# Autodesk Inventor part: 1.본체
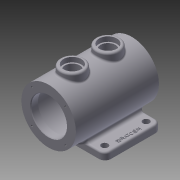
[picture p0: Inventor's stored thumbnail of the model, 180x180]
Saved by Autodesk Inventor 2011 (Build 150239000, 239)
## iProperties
Created: 2014-12
Part Number: 1.본체
Document SubType Name: Modeling
Designer: user
Density: 2.71 g/cm^3
Material: 알루미늄-6061
Mass: 1278.07 g
Surface Area: 1072.68 cm^2
Volume: 471.612 cm^3
Author: user
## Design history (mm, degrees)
sketch "스케치1"
  geometry: L1 (-65, -47.5)-(65, -47.5); L2 (65, -47.5)-(65, 47.5); L3 (65, 47.5)-(-65, 47.5); L4 (-65, 47.5)-(-65, -47.5); L5 (-65, -47.5)-(65, 47.5); 2 further points
  constraints: 11 end point, 2 parallel, 1 coincident, 1 horizontal, 1 midpoint, 1 perpendicular
  dimensions: "d0" = 130 distance of L2.end L3.end; "d1" = 95 distance of L3.end L1.start
extrude "돌출1" new body sketch "스케치1" distance "d2" = 12; taper "d3" = 0 deg
node "작업 평면1"
sketch "스케치2"
  geometry: L1 (0, -12)-(130, -12) reference; L2 (130, 0)-(130, -12) reference; L3 (130, 0)-(0, 0) reference; L4 (0, 0)-(0, -12) reference; C1 r 46 at (65, -50); 2 further points
  constraints: 1 centre point, 1 midpoint, 1 vertical alignment
  dimensions: "d5" = 92 diameter of C1; "d6" = 50 distance from line of L3 C1.centre
extrude "돌출2" join sketch "스케치2" distance "d7" = 140; taper "d8" = 0 deg
sketch "스케치3"
  geometry: L1 (-77.5, 96)-(62.5, 96) reference; L2 (62.5, 96)-(62.5, 4) reference; L3 (62.5, 4)-(47.5, 4) reference; L4 (47.5, 4)-(47.5, 0) reference; L5 (47.5, 0)-(-47.5, 0) reference; L6 (-47.5, 0)-(-47.5, 4) reference; L7 (-47.5, 4)-(-77.5, 4) reference; L8 (-77.5, 4)-(-77.5, 96) reference; L9 (-77.5, 50)-(62.5, 50); L10 (-77.5, 80)-(-65.5, 80); L11 (-65.5, 80)-(-65.5, 84.5); L12 (-62.5, 87.5)-(47.5, 87.5); L13 (50.5, 84.5)-(50.5, 80); L14 (50.5, 80)-(62.5, 80); A1 r 3 centre (-62.5, 84.5) between (-62.5, 87.5) and (-65.5, 84.5); A2 r 3 centre (47.5, 84.5) between (50.5, 84.5) and (47.5, 87.5); 1 further point
  constraints: 12 end point, 4 point on circle, 4 tangent, 2 centre point, 2 midpoint, 2 point on line, 2 vertical, 1 equal radius, 1 horizontal, 1 parallel, 1 perpendicular
  dimensions: "d9" = 60 diameter of L14 L9; "d10" = 75 diameter of L12 L9; "d11" = 60 diameter of L10 L9; "d12" = 12 distance of L13.end L14.end; "d13" = 12 distance of L10.start L10.end; "d14" = 3 radius of A1
revolve "회전1" sketch "스케치3" stored, may be unused: angle "d15" = 90 deg
chamfer "모따기1" distance "d16" = 1; stored, may be unused: second distance "d17" = 2, angle "d18" = 45 deg
node "작업 평면2"
sketch "스케치4"
  geometry: L1 (-46, 62.5)-(46, 62.5) reference; L2 (46, -77.5)-(-46, -77.5) reference; L3 (25.923, -47.5)-(-25.923, -47.5) reference; L4 (25.923, 47.5)-(25.923, -47.5) reference; L5 (-25.923, 47.5)-(25.923, 47.5) reference; L6 (-25.923, -47.5)-(-25.923, 47.5) reference; C1 r 20 at (0, -37.5); C2 r 20 at (0, 22.5); 1 further point
  constraints: 2 centre point, 2 vertical alignment
  dimensions: "d20" = 40 diameter of C1; "d21" = 40 diameter of C2; "d22" = 40 distance from line of C2.centre L1; "d23" = 40 distance from line of L2 C1.centre
extrude "돌출3" join sketch "스케치4" stored distance "d24" = 140; taper "d25" = 0 deg
hole "Hole1" diameter "d28" = 25; stored, may be unused: countersink angle "d32" = 90 deg, drill point angle "d34" = 0 deg; dims "d26" = 10, "d27" = 10, "d29" = 6, "d30" = 30, "d31" = 8, "d33" = 50
hole "Hole2" diameter "d37" = 25; stored, may be unused: countersink angle "d41" = 90 deg, drill point angle "d43" = 0 deg; dims "d35" = 10, "d36" = 10, "d38" = 6, "d39" = 30, "d40" = 8, "d42" = 50
sketch "스케치5"
  geometry: L1 (-37.419, 0)-(0, 0); L2 (0, 0)-(-28.284, 28.284); C1 r 31 at (0, 0) reference; 1 further point
  constraints: 4 end point, 1 horizontal
  dimensions: "d44" = 45 deg angle of L1 L2; "d45" = 40 distance of L1.end L2.end
hole "Hole3" sketch "스케치5" at (-28.284, 28.284) diameter "d46" = 3.242; stored, may be unused: countersink angle "d50" = 90 deg, drill point angle "d52" = 118 deg; dims "d47" = 8, "d48" = 30, "d49" = 8, "d51" = 10
sketch "스케치6"
  geometry: L1 (0, 0)-(33.996, 0); L2 (28.284, -28.284)-(0, 0); C1 r 31 at (0, 0) reference; 1 further point
  constraints: 4 end point, 1 horizontal
  dimensions: "d56" = 45 deg angle of L1 L2; "d57" = 40 distance of L2.start L1.start
hole "Hole4" sketch "스케치6" at (28.284, -28.284) diameter "d58" = 3.242; stored, may be unused: countersink angle "d62" = 90 deg, drill point angle "d64" = 118 deg; dims "d59" = 8, "d60" = 30, "d61" = 8, "d63" = 10
fillet "모깎기1" dims "d68" = 10
fillet "모깎기2" dims "d69" = 3
sketch "스케치7"
  geometry: L1 (-25.923, -44.5)-(-55, -44.5) reference; L2 (-62, -37.5)-(-62, 37.5) reference; L3 (-55, 44.5)-(-25.923, 44.5) reference; L4 (-25.923, -44.5)-(-25.923, 44.5) reference; L5 (-25.923, -77.5)-(-25.923, -44.5) reference; L6 (25.923, -77.5)-(-25.923, -77.5) reference; L7 (25.923, -44.5)-(25.923, -77.5) reference; L8 (55, -44.5)-(25.923, -44.5) reference; L9 (62, 37.5)-(62, -37.5) reference; L10 (25.923, 44.5)-(55, 44.5) reference; L11 (25.923, 62.5)-(25.923, 44.5) reference; L12 (-25.923, 62.5)-(25.923, 62.5) reference; L13 (-25.923, 44.5)-(-25.923, 62.5) reference; L14 (25.923, 44.5)-(25.923, -44.5) reference; L15 (-20.857, 47.5)-(-55, 47.5) reference; L16 (0, 0)-(-6.103, 0); C1 r 5.5 at (-52, 35); C2 r 5.5 at (52, 35); C3 r 5.5 at (-52, -35); C4 r 5.5 at (52, -35); A1 r 7 centre (-55, -37.5) between (-62, -37.5) and (-55, -44.5) reference; A2 r 7 centre (-55, 37.5) between (-55, 44.5) and (-62, 37.5) reference; A3 r 7 centre (55, -37.5) between (55, -44.5) and (62, -37.5) reference; A4 r 7 centre (55, 37.5) between (62, 37.5) and (55, 44.5) reference
  constraints: 4 centre point, 2 end point, 2 symmetric about line, 1 horizontal alignment, 1 parallel, 2 other
  dimensions: "d70" = 11 diameter of C1; "d71" = 12.5 distance from line of C1.centre L15; "d72" = 104 distance of C2.centre C1.centre; "d73" = 52 horizontal distance of C1.centre L16.start; "d74" = 11 diameter of C2
extrude "돌출4" cut sketch "스케치7" stored distance "d75" = 140; taper "d76" = 0 deg
sketch "스케치8"
  geometry: L1 (53.998, -20.739)-(53.998, 20.739); L2 (53.998, 20.739)-(60.002, 20.739); L3 (60.002, 20.739)-(60.002, -20.739); L4 (60.002, -20.739)-(53.998, -20.739); L5 (53.998, -20.739)-(60.002, 20.739); L6 (65, -37.5)-(65, 37.5) reference; C1 r 5.5 at (52, -35) reference; 3 further points
  constraints: 2 end point, 1 coincident, 1 midpoint, 2 other
  dimensions: "d77" = 8 distance from line of point (57, 0) L6; "d78" = 35 vertical distance of point (57, 0) C1.centre
feature "엠보싱1" sketch "스케치8" dims "d0" = 130, "d1" = 95, "d79" = 1, "d80" = 0
fillet "모깎기3" dims "d81" = 5
fillet "모깎기4" dims "d82" = 3
node "솔리드1"
pattern_circular "원형 패턴1" dims angle "d54" = 360 deg
pattern_circular "원형 패턴2" dims angle "d66" = 360 deg
node "투영된 루프1"
node "투영된 루프2"
node "절단 모서리 투영1"
node "절단 모서리 투영2"
other parameters: "d4" = 15, "d19" = 106
